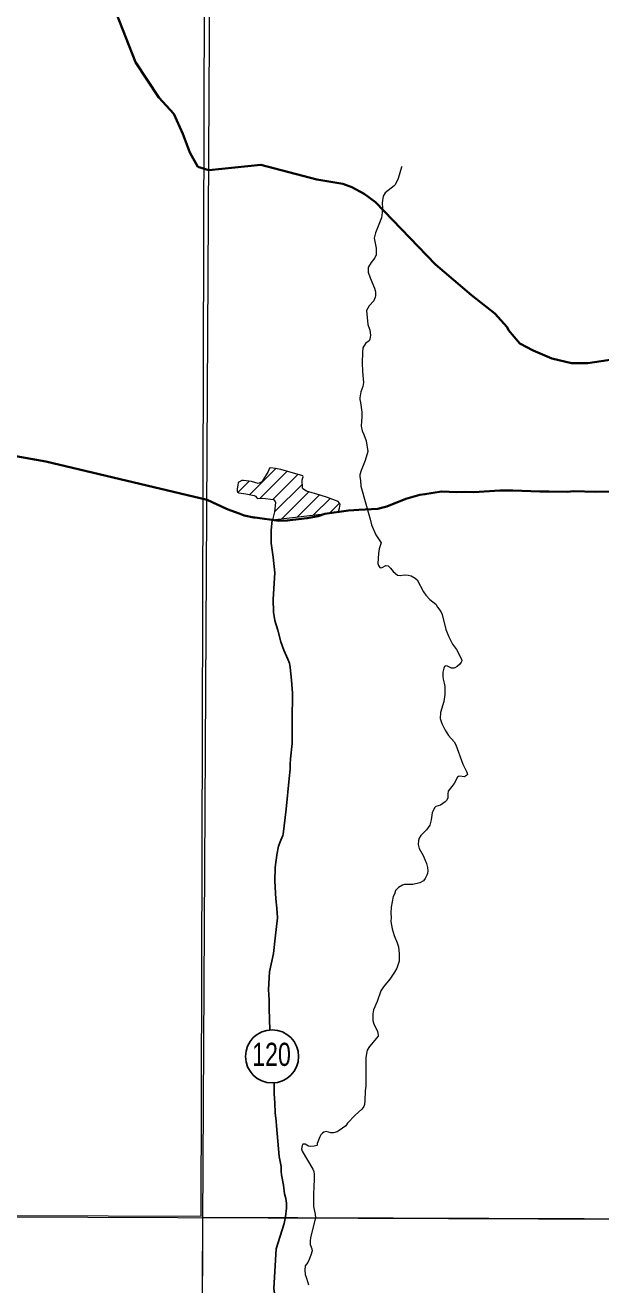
# Model space of a CAD drawing. Extents: x -1643653 to 4543381, y 1624270 to 13878484.
# Drawn here: x 607038 to 608778, y 8909688 to 8913495 of the extents above; entities that cross this region are included whole.
import ezdxf
from ezdxf.enums import TextEntityAlignment as Align

# ---------------------------------------------------------------- set-up
doc = ezdxf.new("R2010")
doc.units = 0
doc.header["$LTSCALE"] = 200
doc.linetypes.add('LONG_DASH_SHORT_DASH', pattern=[9.9, 6, -1.2, 1.5, -1.2])
doc.layers.add('6', color=7, linetype='Continuous', lineweight=13)
doc.layers.add('60', color=7, linetype='Continuous', lineweight=13)

msp = doc.modelspace()

# ---------------------------------------------------------------- linework, layer by layer
at = {"layer": '6'}
for p, q in [((607716.9, 8912076.1), (607795.8, 8912155)), ((607681.7, 8912083.3), (607715.2, 8912116.8)), ((607748, 8912064.7), (607829.5, 8912146.2)), ((607786.9, 8912061.2), (607862.3, 8912136.7)), ((607792, 8912024), (607876, 8912107.9)), ((607813.7, 8912003.2), (607895.2, 8912084.7)), ((607861.8, 8912008.9), (607928.2, 8912075.3)), ((607910, 8912014.6), (607959.8, 8912064.4)), ((607958.1, 8912020.3), (607988.1, 8912050.4)), ((574653.9, 8910009.3), (626625.7, 8909822.1))]:
    msp.add_line(p, q, dxfattribs=at)
for points in [[(607657.7, 8924743.3), (607574.2, 8909874.9), (607492.3, 8896026.7)], [(608177, 8913067.6), (608176.1, 8913066), (608165.7, 8913031.8), (608156.9, 8913012.1), (608153.7, 8913008.8), (608126.6, 8912988), (608120, 8912977.9), (608117.8, 8912957.8), (608118.1, 8912941.7), (608117.4, 8912928.9), (608115.2, 8912912.8), (608097.1, 8912867.6), (608093.4, 8912851.5), (608094, 8912846), (608099.3, 8912820.9), (608099.7, 8912800.3), (608095.4, 8912791.9), (608084, 8912778), (608076, 8912764.8), (608074.7, 8912761.3), (608075.5, 8912748.7), (608080.7, 8912731.7), (608094.4, 8912700.1), (608097.1, 8912689.1), (608097.3, 8912677.2), (608096.6, 8912673.1), (608092, 8912661.9), (608078.3, 8912646.9), (608069.7, 8912632.1), (608074, 8912590.5), (608080, 8912572.6), (608082.5, 8912558.2), (608079.8, 8912546.2), (608077.6, 8912541), (608075.2, 8912538.6), (608066.9, 8912532.8), (608059.2, 8912520.1), (608057.5, 8912505.4), (608057, 8912474.8), (608057.7, 8912447.7), (608061, 8912415.3), (608059, 8912402.5), (608052.8, 8912386.3)], [(608052.8, 8912386.3), (608049.7, 8912368.8), (608050, 8912363.6), (608052.3, 8912354.9), (608055.7, 8912325.2), (608056, 8912311.6), (608054.1, 8912282.7), (608056.9, 8912268.3), (608062.4, 8912258), (608069.1, 8912238.4), (608073.7, 8912205.9), (608066.3, 8912178.9), (608053.7, 8912149.1), (608050.2, 8912135.5), (608049.9, 8912129.3), (608052.3, 8912118.7), (608052.6, 8912101.2)], [(607878.1, 8912130.1), (607877.4, 8912132.3), (607811.4, 8912151.5), (607794.5, 8912155.3), (607779.3, 8912157.1), (607777.1, 8912155.8), (607773.1, 8912145.8), (607756, 8912117.2), (607753.7, 8912114.4), (607745.5, 8912110.6), (607742.3, 8912110.1), (607722.3, 8912115.9), (607698.1, 8912119.1), (607693.1, 8912118.7), (607683.7, 8912114.1), (607681.7, 8912112.2), (607681.5, 8912104.9), (607679.4, 8912093.4), (607679.2, 8912087.8), (607680.2, 8912084.6), (607684.2, 8912081.2), (607705.1, 8912078.8), (607730.7, 8912073), (607734.4, 8912071.3), (607738.5, 8912066.1), (607740.8, 8912064.6), (607756.8, 8912064.9), (607787.7, 8912061.1), (607790.3, 8912060), (607793.6, 8912055.2), (607794.5, 8912052.4), (607792.1, 8912024), (607785.6, 8911999.8), (607984.4, 8912023.4)], [(607984.4, 8912023.4), (607988.4, 8912035), (607990.7, 8912047.1), (607984.7, 8912054.7), (607952.5, 8912067.2), (607929.9, 8912074.8), (607888.4, 8912086.6), (607877.5, 8912093.2), (607876.3, 8912096), (607875.7, 8912120.9), (607878.1, 8912130.1)], [(608052.6, 8912101.2), (608080.6, 8912001.5), (608085, 8911985.1), (608098.3, 8911954.4), (608114.1, 8911930.6)], [(608114.1, 8911930.6), (608108.5, 8911912.4), (608105.9, 8911898.3), (608104.2, 8911867.9), (608106, 8911862.2), (608110.6, 8911856.1), (608113.1, 8911854.8), (608117.7, 8911855.7), (608128, 8911861.3), (608135, 8911860.6), (608142.3, 8911854), (608150.3, 8911843.8), (608163.7, 8911832.7), (608171.8, 8911832), (608184.9, 8911833.2), (608196, 8911832.8), (608205.5, 8911831), (608216.8, 8911823.8), (608223, 8911818.1), (608242, 8911781.7), (608249.2, 8911771.6), (608261.1, 8911759.4), (608279.3, 8911744.8), (608285.1, 8911735.4)], [(608285.1, 8911735.4), (608294.4, 8911723.1), (608298.6, 8911713.6), (608309.6, 8911667.9), (608318.4, 8911645.8), (608330.3, 8911623.7), (608341.8, 8911607.5), (608356.8, 8911578.9), (608357.8, 8911573.4), (608356.6, 8911569.3), (608351.9, 8911563.7), (608344.4, 8911556.9), (608337.1, 8911552), (608334, 8911551), (608327.4, 8911551.2), (608315.1, 8911557), (608310.1, 8911558.1), (608306.1, 8911556.1), (608303.3, 8911551.1), (608301.1, 8911539.5), (608300.6, 8911528.4), (608301.8, 8911518.2), (608305.1, 8911506.3), (608306.7, 8911496), (608306.4, 8911471.6), (608304.1, 8911450.3), (608294.1, 8911417.1), (608292.9, 8911399.4), (608297.6, 8911384), (608308.3, 8911363.7), (608318, 8911348.3), (608334.8, 8911328.6), (608339.7, 8911319.4), (608360.9, 8911261.1), (608373.3, 8911237.5), (608375, 8911230.3), (608372.7, 8911227.3)], [(608372.7, 8911227.3), (608372.7, 8911227.3), (608365.8, 8911223.3), (608351.4, 8911225.4), (608348.4, 8911224.5), (608345.5, 8911221.6), (608334.8, 8911202.7), (608316.4, 8911179.4), (608315.5, 8911171.7), (608315.6, 8911158.5), (608311.6, 8911151.9), (608307.3, 8911147.5), (608293.6, 8911136.9), (608280, 8911133), (608275.9, 8911129.4), (608268.8, 8911114.5), (608265.9, 8911093.2), (608261.9, 8911077.1), (608251.5, 8911062.7), (608234.4, 8911045.7), (608229.6, 8911037.8), (608226.7, 8911030.1), (608226, 8911018.3), (608229.5, 8911006.7), (608241.4, 8910985), (608251.6, 8910961.2), (608254.2, 8910949.4), (608255.3, 8910939.2), (608254.1, 8910930.4), (608252.7, 8910925.9), (608247.8, 8910915.8), (608242.3, 8910908.2), (608231, 8910902.2), (608210.4, 8910897.2), (608184.7, 8910897.9), (608178.9, 8910895.7), (608167, 8910888.8), (608158.1, 8910879.6), (608154.4, 8910868.3), (608151.1, 8910860.9), (608144.3, 8910828.8), (608143.3, 8910810.6), (608144.4, 8910798), (608143.9, 8910785.4), (608147.5, 8910763.3), (608153.7, 8910743.5), (608162.5, 8910721.4), (608166.3, 8910708.8), (608168.7, 8910688.2), (608168.3, 8910666.1), (608161.6, 8910644.7), (608155.1, 8910632.9), (608140.4, 8910611.9), (608121.6, 8910588.8), (608113.6, 8910576.1), (608102.1, 8910544.4), (608090.7, 8910519.2), (608088.7, 8910506.7), (608089.2, 8910486.1), (608091.9, 8910475.9), (608103.1, 8910454.4), (608105.7, 8910441.4), (608104.8, 8910439.1), (608078.6, 8910407.5), (608072, 8910396.6)], [(608072, 8910396.6), (608069.6, 8910387.1), (608068.1, 8910373.8), (608068.3, 8910308.2), (608067.6, 8910288.4), (608066.2, 8910273.5), (608065.1, 8910243.4), (608063.5, 8910232.3), (608061.9, 8910227), (608055.7, 8910219), (608035.7, 8910200.6), (608012.5, 8910176.3), (608007.7, 8910168.6), (607987.3, 8910153.6), (607980.8, 8910149.9), (607970.7, 8910147.2), (607961.9, 8910147.3), (607948.5, 8910151.3), (607941.1, 8910148.7), (607937.3, 8910146.5), (607932.1, 8910141.4), (607928.5, 8910134.9), (607921.3, 8910114.9), (607920.8, 8910110.1), (607919.9, 8910108.9), (607911.6, 8910106.4), (607900.5, 8910105.6), (607894.4, 8910107.2), (607884.3, 8910112.4), (607879.3, 8910113.2), (607877.1, 8910112.3), (607875.3, 8910108.4), (607873.8, 8910098.7), (607875, 8910091.5), (607907.8, 8910037.4), (607910.9, 8910030.1), (607911.9, 8910021.7)], [(607911.9, 8910021.7), (607911.9, 8910002.7), (607911.9, 8910002.7), (607910.6, 8909987.8), (607909.5, 8909957.7), (607910.2, 8909924.6), (607914.4, 8909900.9), (607915.5, 8909889.9), (607900.2, 8909830.5)], [(607900.2, 8909830.5), (607900.1, 8909819.3), (607900, 8909809.1), (607905, 8909796.9), (607905.6, 8909789.5)], [(607905.8, 8909790.3), (607901.8, 8909777.5), (607896.7, 8909764.3), (607892.5, 8909755.2), (607884.8, 8909745.4), (607883.4, 8909732.4), (607884.8, 8909718.5), (607888.1, 8909707.3), (607892.1, 8909698.2), (607894.9, 8909687.9)]]:
    msp.add_lwpolyline(points, dxfattribs=at)
for points in [[(607600.8, 8920952.4), (596639.8, 8920989.8), (596608.8, 8909934.4), (607569.8, 8909894.9)], [(618535.2, 8909853.3), (607574.3, 8909890.7), (607543.3, 8898835.3), (618504.2, 8898795.8)]]:
    msp.add_lwpolyline(points, close=True, dxfattribs=at)
at = {"layer": '6', "linetype": 'LONG_DASH_SHORT_DASH', "lineweight": 35}
for points in [[(606539.4, 8914008.9), (606574.4, 8913973.3), (606620.1, 8913944.6), (606665.8, 8913915.9), (606715.2, 8913894.3), (606775.2, 8913886.7), (606909.9, 8913928), (606952.4, 8913938.2), (606991.4, 8913944.9), (607044.4, 8913944.5), (607100.9, 8913933.4), (607185.1, 8913863.8), (607217.8, 8913819.4), (607258.2, 8913730.6), (607313.1, 8913532.2), (607371.9, 8913383.3), (607441.7, 8913276.6), (607487.2, 8913226.8), (607515, 8913166.4), (607535.7, 8913109.7), (607560.1, 8913067.1), (607593.6, 8913056.5)], [(607593.6, 8913056.5), (607750.3, 8913072.5), (607919.5, 8913028.9), (607998, 8913015.2), (608025.9, 8913004.8), (608063.1, 8912985.3), (608097.6, 8912959.8), (608278.6, 8912771.5), (608387.1, 8912679.3), (608457.5, 8912623.9), (608495.5, 8912582.2), (608499.3, 8912573), (608533.8, 8912533.1), (608573.8, 8912511.3), (608630.1, 8912487.7), (608690.1, 8912473.2), (608739.3, 8912473), (608819.6, 8912485.1)]]:
    msp.add_lwpolyline(points, dxfattribs=at)
at = {"layer": '6', "lineweight": 40}
for points in [[(605772.2, 8912307.9), (605897.3, 8912328.7), (606065.1, 8912373.9), (606133.7, 8912373.3), (606372, 8912330.1), (606873.2, 8912216.1), (607100.6, 8912175.7), (607588, 8912059.9)], [(608046.5, 8912030.3), (608104.6, 8912033.5), (608115.8, 8912035.7), (608131.7, 8912040.1), (608189.1, 8912063.1), (608231, 8912075.3), (608246.4, 8912077.2), (608296.7, 8912085.9), (608343.5, 8912083.2), (608370.2, 8912084), (608394.4, 8912083.7), (608472.6, 8912088.7), (608512.2, 8912088.3), (608594.2, 8912085), (608621.4, 8912085.3), (608678.1, 8912084.6), (608696.2, 8912086.1), (608762.8, 8912084.9), (608854.3, 8912085.7), (608880.1, 8912084.5), (608921.7, 8912085.7), (608991, 8912084.9), (609098.7, 8912084.9), (609159.5, 8912084.9)], [(607588, 8912059.9), (607646.9, 8912033.5), (607660.1, 8912027.5), (607685.1, 8912019.4), (607700.3, 8912012.4), (607729.4, 8912007.2), (607733.2, 8912006.7)], [(607733.2, 8912006.7), (607805.3, 8911997.2), (607830.4, 8911997.3), (607890.4, 8912004.8), (607923.9, 8912011.2)], [(607923.9, 8912011.2), (607944.1, 8912017.6), (608015.2, 8912027.8), (608031.4, 8912029.4), (608046.5, 8912030.3)]]:
    msp.add_lwpolyline(points, dxfattribs=at)
at = {"layer": '6', "lineweight": 25}
for points in [[(607784.9, 8911999.6), (607782.1, 8911967.5), (607781.3, 8911929.5), (607788, 8911886.9), (607792.5, 8911839.5), (607788.3, 8911760.4), (607788.9, 8911720.9), (607793.1, 8911695.9), (607802, 8911666.8), (607810.5, 8911630.6), (607820.1, 8911605.6), (607832.4, 8911579), (607837.3, 8911566.1), (607839.5, 8911553.2), (607843.7, 8911515.3), (607845.8, 8911475.8), (607845.1, 8911393), (607845.4, 8911323.6), (607839.9, 8911277.2), (607839.1, 8911261.7), (607839.2, 8911246.2), (607835.7, 8911217.9), (607827.2, 8911125.4)], [(607827.2, 8911125.4), (607818.3, 8911050.1), (607817.3, 8911045.7), (607811.1, 8911032.1), (607804.2, 8911013.7), (607798.7, 8910987.7)], [(607798.7, 8910987.7), (607798.4, 8910986.3), (607793.6, 8910949.1), (607793.1, 8910907.6), (607795.5, 8910854.2), (607799.3, 8910825.8), (607801.4, 8910796.7), (607794, 8910735.7)], [(607794, 8910735.7), (607788.4, 8910689.2), (607776.8, 8910633.3), (607773.3, 8910579.9), (607775.9, 8910548.2), (607775.9, 8910522), (607777.9, 8910458.8)], [(607790.9, 8910298.5), (607791.2, 8910292), (607790.9, 8910265.3), (607792.9, 8910237.8), (607794, 8910207.8), (607797.2, 8910181.9), (607797.8, 8910168.2), (607805.9, 8910075.3), (607811.7, 8910045.2), (607812, 8910030.6), (607813.2, 8910020.3), (607819.2, 8909989.3), (607822.2, 8909962.7), (607826.4, 8909948.1), (607828.6, 8909934.3), (607828.1, 8909919.8), (607824.7, 8909893.1), (607821.4, 8909873.3)], [(607821.4, 8909873.3), (607797, 8909796.1), (607789.4, 8909676.9), (607793.4, 8909647.3), (607855.8, 8909325.6)]]:
    msp.add_lwpolyline(points, dxfattribs=at)
msp.add_circle((607784.4, 8910378), 80.3, dxfattribs=at)
at = {"layer": '60', "lineweight": 25}
msp.add_spline([(814781, 9009175.5), (814787.2, 9009173.4), (814796.9, 9009173.4), (814799.4, 9009172.4), (814805.1, 9009174.5), (814805.6, 9009176.5), (814811.7, 9009179.5), (814811.7, 9009179.5), (814801.5, 9009181), (814790.7, 9009181.5), (814784.1, 9009183.1), (814777.4, 9009185.1), (814778.4, 9009175.5)], degree=3, dxfattribs=at)

# ---------------------------------------------------------------- texts
at = {"layer": '6', "width": 0.75}
msp.add_text('120', height=70, dxfattribs=at).set_placement((607782.8, 8910349.3), align=Align.CENTER)

doc.saveas('drawing.dxf')
